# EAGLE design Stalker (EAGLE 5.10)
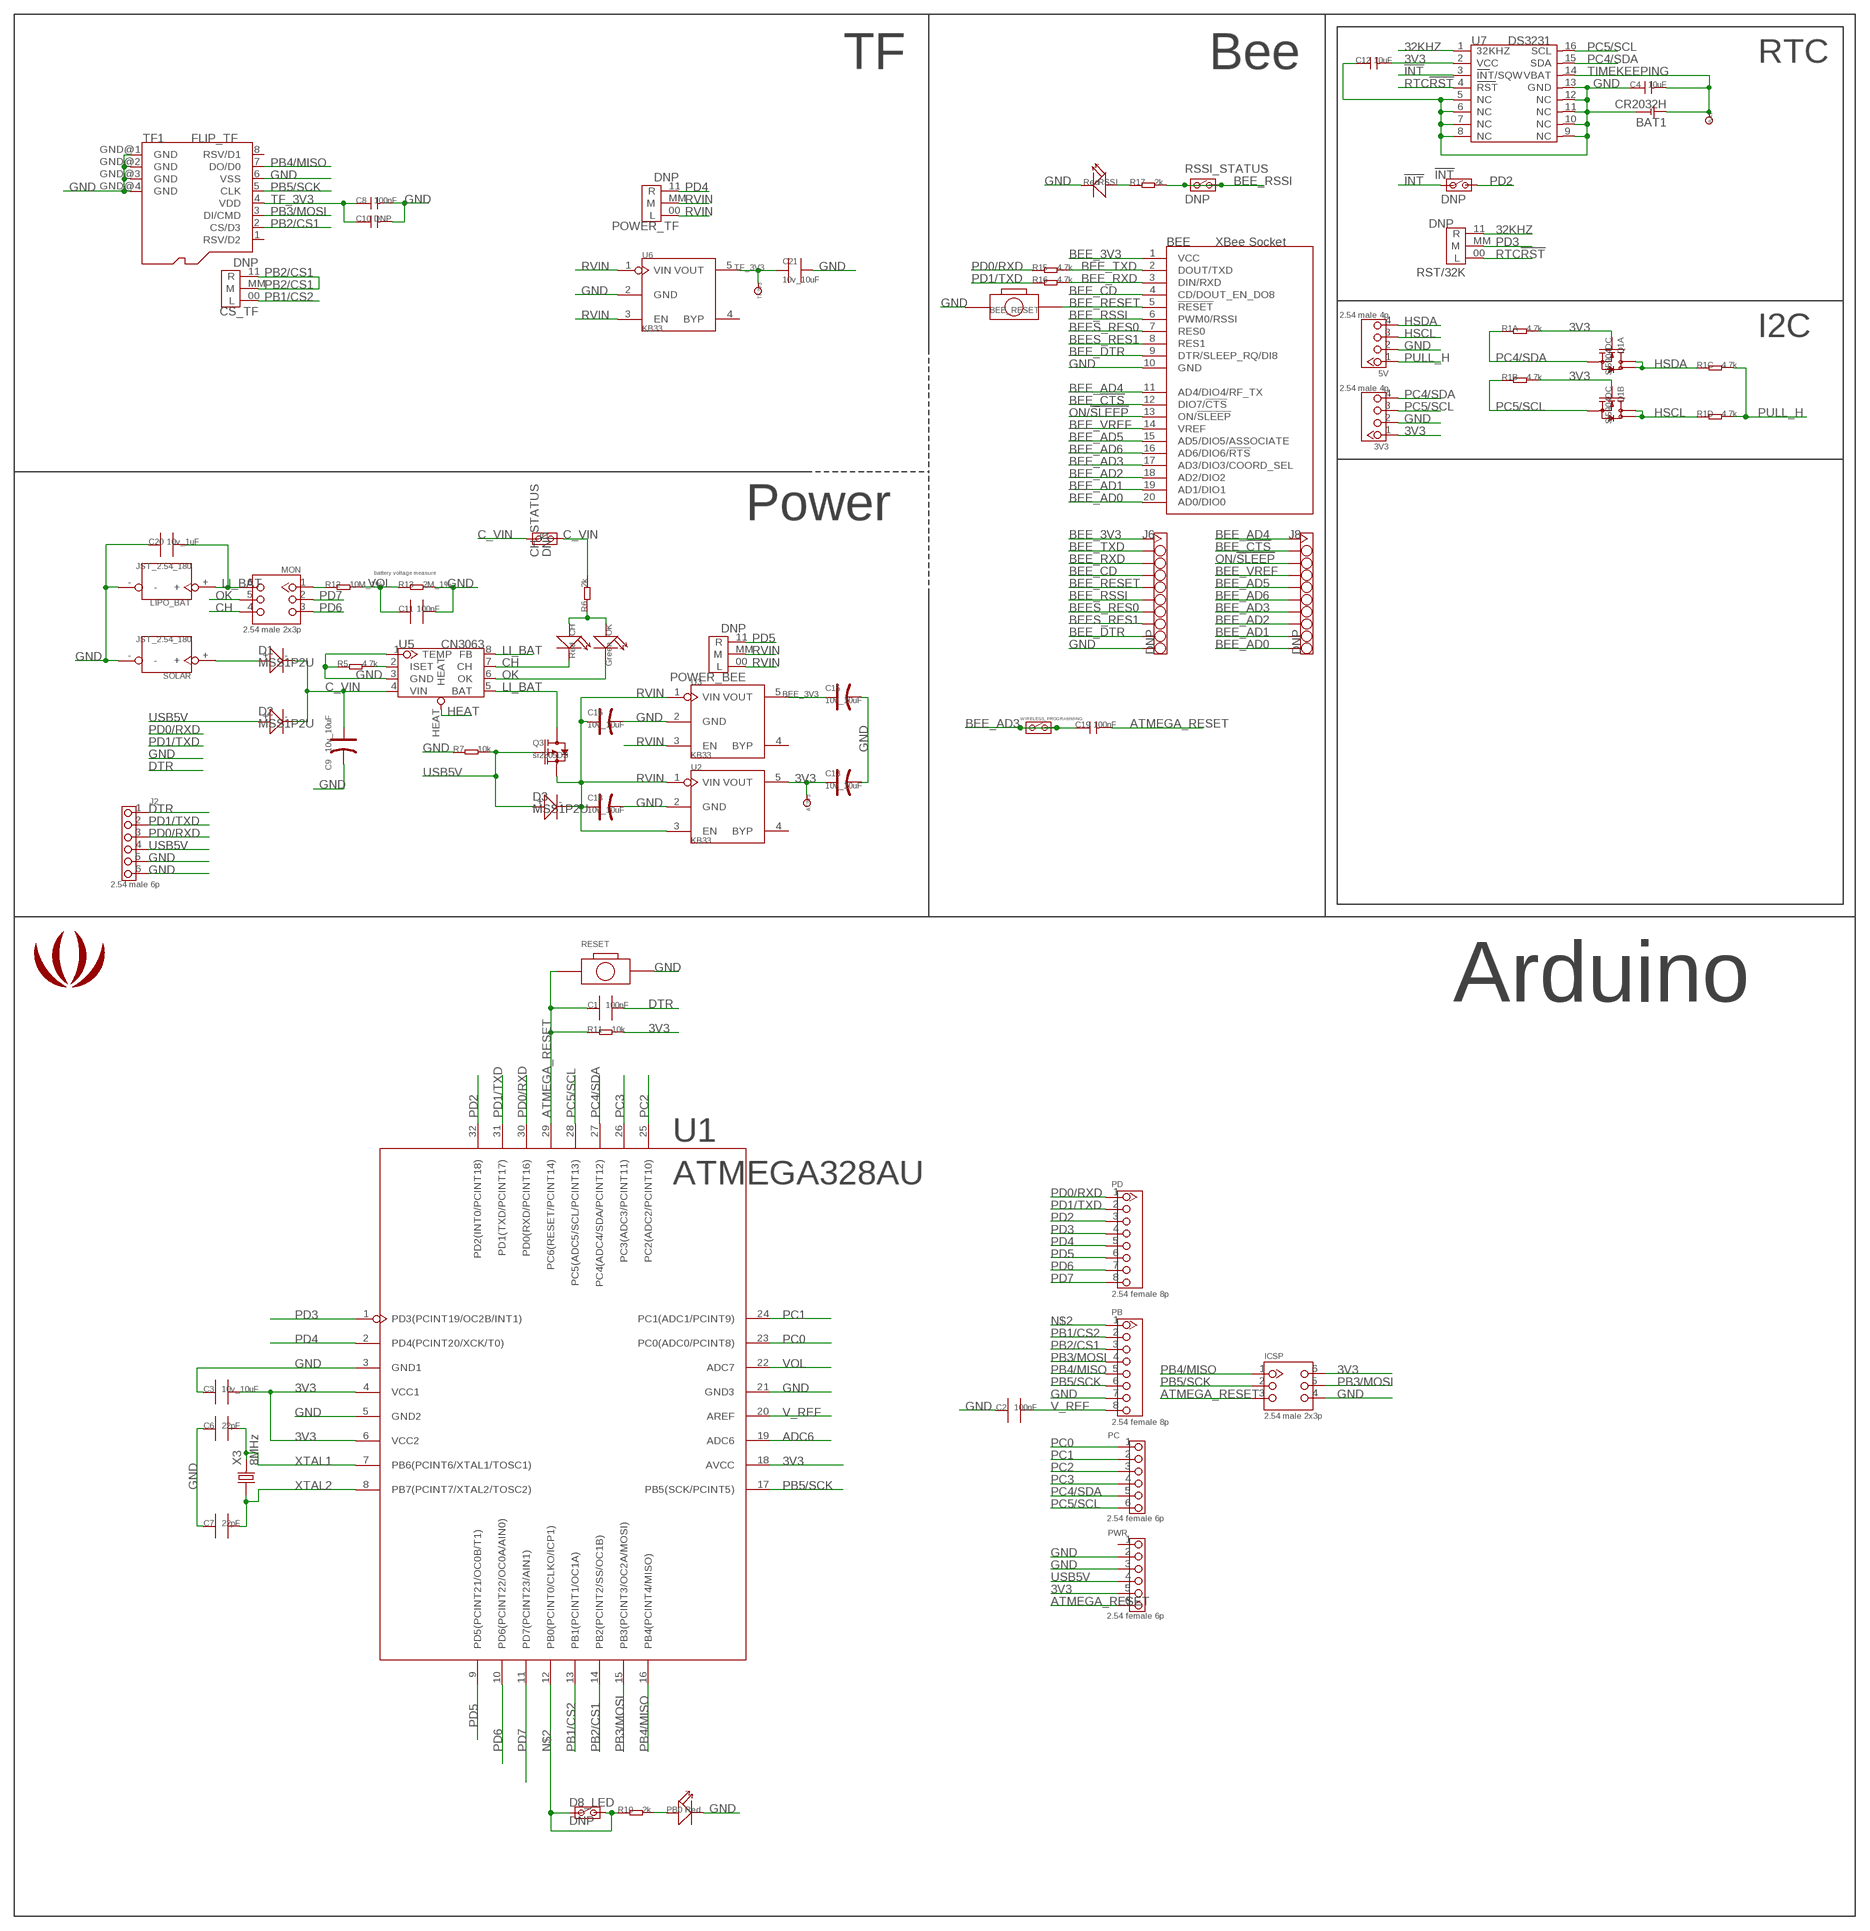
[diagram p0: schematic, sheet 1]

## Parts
3V3  2.54 male 4p  HEADER-4P-2.54  [4P-2.54-LEADED]
5V  2.54 male 4p  HEADER-4P-2.54  [4P-2.54-LEADED]
!INT  DNP  JP_SW  [JP_SW]
AT3V3  DNP  TEST_POINT_SIZE_3030  [TP_3535]
BAT  DNP  TEST_POINT_SIZE_3030  [TP_3535]
BAT1  CR2032H  [CR2032H]
BEE  XBee Socket  BEEO  [BEE]
BEE_RESET  3.8x6.1 button  BOTTON_1_SMD  [BOTTON_1]
C1  100nF  006-C0603  [0603@1]
C2  100nF  006-C0603  [0603@1]
C3  10v_10uF  006-C0805  [0805@1]
C4  10uF  C-0805  [0805]
C6  22pF  006-C0603  [0603@1]
C7  22pF  006-C0603  [0603@1]
C8  100nF  C-0603  [0603]
C9  10v_10uF  006-CAP_AVX_B  [AVX_B]
C10  DNP  C-0603  [0603]
C11  100nF  006-C0603  [0603@1]
C12  10uF  C-0805  [0805]
C13  10v_10uF  006-CAP_AVX_B  [AVX_B]
C15  10v_10uF  006-CAP_AVX_B  [AVX_B]
C16  10v_10uF  006-CAP_AVX_B  [AVX_B]
C18  10v_10uF  006-CAP_AVX_B  [AVX_B]
C19  100nF  C-0603  [0603]
C20  10v_1uF  006-C0805  [0805@1]
C21  10v_10uF  006-C0805  [0805@1]
CH  Red  007-LED0603  [D0603]
CH_STATUS  DNP  JP_SW  [JP_SW]
CS_TF  DNP  JUMPER  [JUMPER]
D1  MSS1P2U  010-DMSS1P2U  [D1005]
D2  MSS1P2U  010-DMSS1P2U  [D1005]
D3  MSS1P2U  010-DMSS1P2U  [D1005]
D8_LED  DNP  JP_SW  [JP_SW]
ICSP  2.54 male 2x3p  HEADER-2X3P-2.54  [2X3P-2.54-LEADED]
J2  2.54 male 6p  HEADER-6P-LEADED-2.54  [6P-2.54-LEADED]
J6  DNP  HEADER_1X10DD  [HEADER_1X10]
J8  DNP  HEADER_1X10DD  [HEADER_1X10]
LIPO_BAT  JST_2.54_180  PWR2P_180  [PWR_1X2]
LOGO1  LOGO  [LOGO_RO]
MON  2.54 male 2x3p  HEADER-2X3P-2.54  [2X3P-2.54-LEADED]
OK  Green  007-LED0603  [D0603]
PB  2.54 female 8p  HEADER-8P-2.54-LEADED  [8P-2.54-LEADED]
PB0  Red  007-LED0603  [D0603]
PC  2.54 female 6p  HEADER-6P-LEADED-2.54  [6P-2.54-LEADED]
PD  2.54 female 8p  HEADER-8P-2.54-LEADED  [8P-2.54-LEADED]
POWER_BEE  DNP  JUMPER  [JUMPER]
POWER_TF  DNP  JUMPER  [JUMPER]
PWR  2.54 female 6p  HEADER-6P-LEADED-2.54  [6P-2.54-LEADED]
Q1  Si5904DC  010-DUAL-N-MOSFET_1206-8  [1206-8]
Q3  si2305DS  010-P-MOSFETSOT23  [SOT23]
R1  4.7k  005-4R_1206  [R1206-8]
R5  4.7k  005-R0603  [0603@1]
R6  2k  005-R0603  [0603@1]
R7  10k  005-R0603  [0603@1]
R10  2k  005-R0603  [0603@1]
R11  10k  005-R0603  [0603@1]
R12  10M_1%  005-R0603  [0603@1]
R13  2M_1%  005-R0603  [0603@1]
R15  4.7k  005-R0603  [0603@1]
R16  4.7k  005-R0603  [0603@1]
R17  2k  005-R0603  [0603@1]
RESET  3.8x6.1 button  BOTTON_1_SMD  [BOTTON_1]
RSSI  Red  007-LED0603  [D0603]
RSSI_STATUS  DNP  JP_SW  [JP_SW]
RST/32K  DNP  JUMPER  [JUMPER]
SOLAR  JST_2.54_180  PWR2P_180  [PWR_1X2]
TF1  FLIP_TF  [FLIP_TF]
TF3V3  DNP  TEST_POINT_SIZE_3030  [TP_3535]
U1  ATMEGA328AU  ATMEGA168-20AU  [ATMEGA168-20AU]
U2  KB33  MIC5025_X.X  [SOT23-5]
U3  KB33  MIC5025_X.X  [SOT23-5]
U5  CN3063  CN3083  [SOP8]
U6  KB33  MIC5025_X.X  [SOT23-5]
U7  DS3231  [SO16-W]
WIRELESS_PROGRAMMING  DNP  JP_SW  [JP_SW]
X3  8MHz  011-CRYSTALHC49S  [HC49/S]

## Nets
3V3: 3V3.1 AT3V3.T C3.2 C12.2 C13.+ ICSP.6 PWR.5 Q1.2(A:G) Q1.4(B:G) R1.7 R1.8 R11.2 U1.4(VCC1) U1.6(VCC2) U1.18(AVCC) U2.5(VOUT) U7.2(VCC)
32KHZ: RST/32K.11(R) U7.1(32KHZ)
!INT: !INT.1 U7.3(INT/SQW)
ADC6: U1.19(ADC6)
ATMEGA_RESET: C1.1 C19.2 ICSP.3 PWR.6 R11.1 RESET.1 U1.29(PC6(RESET/PCINT14))
BEE_3V3: BEE.1(VCC) C15.+ J6.1 U3.5(VOUT)
BEE_!CTS: BEE.12(DIO7/!CTS) J8.2
BEE_AD0: BEE.20(AD0/DIO0) J8.10
BEE_AD1: BEE.19(AD1/DIO1) J8.9
BEE_AD2: BEE.18(AD2/DIO2) J8.8
BEE_AD3: BEE.17(AD3/DIO3/COORD_SEL) C19.1 J8.7 WIRELESS_PROGRAMMING.1 WIRELESS_PROGRAMMING.2
BEE_AD4: BEE.11(AD4/DIO4/RF_TX) J8.1
BEE_AD5: BEE.15(AD5/DIO5/ASSOCIATE) J8.5
BEE_AD6: BEE.16(AD6/DIO6/!RTS) J8.6
BEE_CD: BEE.4(CD/DOUT_EN_DO8) J6.4
BEE_DTR: BEE.9(DTR/SLEEP_RQ/DI8) J6.9
BEE_RESET: BEE.5(!RESET) BEE_RESET.P$2 J6.5
BEE_RSSI: BEE.6(PWM0/RSSI) J6.6 R17.2 RSSI_STATUS.1 RSSI_STATUS.2
BEE_RXD: BEE.3(DIN/RXD) J6.3 R16.2
BEE_TXD: BEE.2(DOUT/TXD) J6.2 R15.2
BEE_VREF: BEE.14(VREF) J8.4
BEES_RES0: BEE.7(RES0) J6.7
BEES_RES1: BEE.8(RES1) J6.8
C_VIN: C9.+ CH_STATUS.1 CH_STATUS.2 D1.- D2.- R6.2 U5.4(VIN)
CH: CH.- MON.4 U5.7(CH)
DTR: C1.2 J2.1
GND: 3V3.2 5V.2 BAT1.- BEE.10(GND) BEE_RESET.1 C2.1 C3.1 C4.1 C6.1 C7.1 C8.2 C9.- C10.2 C11.2 C12.1 C13.- C15.- C16.- C18.- C20.1 C21.2 ICSP.4 J2.5 J2.6 J6.10 LIPO_BAT.- PB0.- PB.7 PWR.2 PWR.3 R5.1 R7.1 R13.2 RESET.P$2 RSSI.- SOLAR.- TF1.6(VSS) TF1.GND@1(GND) TF1.GND@2(GND) TF1.GND@3(GND) TF1.GND@4(GND) U1.3(GND1) U1.5(GND2) U1.21(GND3) U2.2(GND) U3.2(GND) U5.1(TEMP) U5.3(GND) U6.2(GND) U7.5(NC) U7.6(NC) U7.7(NC) U7.8(NC) U7.9(NC) U7.10(NC) U7.11(NC) U7.12(NC) U7.13(GND)
HEAT: U5.HEAT
HSCL: 5V.3 Q1.5(B:D) Q1.6(B:D) R1.4
HSDA: 5V.4 Q1.7(A:D) Q1.8(A:D) R1.3
LI_BAT: C20.2 LIPO_BAT.+ MON.6 Q3.3(D) U5.5(BAT) U5.8(FB)
N$1: PB0.+ R10.2
N$2: D8_LED.1 D8_LED.2 PB.1 R10.1 U1.12(PB0(PCINT0/CLKO/ICP1))
N$3: D1.+ SOLAR.+
N$5: R5.2 U5.2(ISET)
N$6: R17.1 RSSI.+
N$8: CH.+ OK.+ R6.1
N$15: MON.1 R12.1
OK: MON.5 OK.- U5.6(OK)
ON/!SLEEP: BEE.13(ON/!SLEEP) J8.3
PB1/CS2: CS_TF.00(L) PB.2 U1.13(PB1(PCINT1/OC1A))
PB2/CS1: CS_TF.11(R) CS_TF.MM(M) PB.3 TF1.2(CS/D3) U1.14(PB2(PCINT2/SS/OC1B))
PB3/MOSI: ICSP.5 PB.4 TF1.3(DI/CMD) U1.15(PB3(PCINT3/OC2A/MOSI))
PB4/MISO: ICSP.1 PB.5 TF1.7(DO/D0) U1.16(PB4(PCINT4/MISO))
PB5/SCK: ICSP.2 PB.6 TF1.5(CLK) U1.17(PB5(SCK/PCINT5))
PC0: PC.1 U1.23(PC0(ADC0/PCINT8))
PC1: PC.2 U1.24(PC1(ADC1/PCINT9))
PC2: PC.3 U1.25(PC2(ADC2/PCINT10))
PC3: PC.4 U1.26(PC3(ADC3/PCINT11))
PC4/SDA: 3V3.4 PC.5 Q1.1(A:S) R1.1 U1.27(PC4(ADC4/SDA/PCINT12)) U7.15(SDA)
PC5/SCL: 3V3.3 PC.6 Q1.3(B:S) R1.2 U1.28(PC5(ADC5/SCL/PCINT13)) U7.16(SCL)
PD0/RXD: J2.3 PD.1 R15.1 U1.30(PD0(RXD/PCINT16))
PD1/TXD: J2.2 PD.2 R16.1 U1.31(PD1(TXD/PCINT17))
PD2: !INT.2 PD.3 U1.32(PD2(INT0/PCINT18))
PD3: PD.4 RST/32K.MM(M) U1.1(PD3(PCINT19/OC2B/INT1))
PD4: PD.5 POWER_TF.11(R) U1.2(PD4(PCINT20/XCK/T0))
PD5: PD.6 POWER_BEE.11(R) U1.9(PD5(PCINT21/OC0B/T1))
PD6: MON.3 PD.7 U1.10(PD6(PCINT22/OC0A/AIN0))
PD7: MON.2 PD.8 U1.11(PD7(PCINT23/AIN1))
PULL_H: 5V.1 R1.5 R1.6
RTC!RST: RST/32K.00(L) U7.4(RST)
RVIN: C16.+ C18.+ D3.- POWER_BEE.00(L) POWER_BEE.MM(M) POWER_TF.00(L) POWER_TF.MM(M) Q3.2(S) U2.1(VIN) U2.3(EN) U3.1(VIN) U3.3(EN) U6.1(VIN) U6.3(EN)
TF_3V3: C8.1 C10.1 C21.1 TF1.4(VDD) TF3V3.T U6.5(VOUT)
TIMEKEEPING: BAT1.+ BAT.T C4.2 U7.14(VBAT)
USB5V: D2.+ D3.+ J2.4 PWR.4 Q3.1(G) R7.2
V_REF: C2.2 PB.8 U1.20(AREF)
VOL: C11.1 R12.2 R13.1 U1.22(ADC7)
XTAL1: C6.2 U1.7(PB6(PCINT6/XTAL1/TOSC1)) X3.2
XTAL2: C7.2 U1.8(PB7(PCINT7/XTAL2/TOSC2)) X3.1
Unconnected: PWR.1 TF1.1(RSV/D2) TF1.8(RSV/D1) U2.4(BYP) U3.4(BYP) U6.4(BYP)

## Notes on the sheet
- TF | Bee | RTC
- I2C
- Power
- battery voltage measure
- Arduino

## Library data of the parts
3V3 5V = Connector:HEADER-4P
!INT CH_STATUS D8_LED RSSI_STATUS WIRELESS_PROGRAMMING = CPT_SMD:JP_SW
AT3V3 BAT TF3V3 = For_Test_Albert:TEST_POINT
BAT1 = BAT:CR2032H
BEE = EXT_moudle:BEE
BEE_RESET RESET = CPT_SMD:BOTTON_1
C1-C3 C6 C7 C11 C20 C21 = Discrete:006-C*: Ceramic Capacitors
C4 C8 C10 C12 C19 = Discrete:C*: Ceramic Capacitors
C9 C13 C15 C16 C18 = Discrete:006-CAP*: Electrolytic Capacitors,Tantalum Capacitors and Super Capacitors
CH OK PB0 RSSI = Discrete:007-LED*
CS_TF POWER_BEE POWER_TF RST/32K = CPT_SMD:JUMPER
D1-D3 = Discrete:010-D*
ICSP MON = Connector:HEADER-2X3P
J2 PC PWR = Connector:HEADER-6P
J6 J8 = CONNECTER:HEADER_1X10
LIPO_BAT SOLAR = CONNECTER:PWR2P
LOGO1 = logo:LOGO
PB PD = Connector:HEADER-8P
Q1 = Discrete:010-DUAL-N-MOSFET*: Si5902BDC Si5904DC Si5908DC Si5920DC
Q3 = Discrete:010-P-MOSFET*: Si2305DS Si2323CDS
R1 = Discrete:005-4R*: Resistor Array
R5-R7 R10-R13 R15-R17 = Discrete:005-R*
TF1 = Holders:FLIP_TF: http://garden.seeedstudio.com/images/e/e4/Flip_TF_Holder.jpg
U1 = IC_SMD:ATMEGA168-20AU
U2 U3 U6 = ICs_v54:MIC5025_X.X
U5 = ICs_v54:CN3083
U7 = IC:DS3231
X3 = Discrete:011-CRYSTAL*: CRYSTAL

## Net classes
0 default: width 0.152 mm, drill 0.305 mm, clearance 0.152 mm

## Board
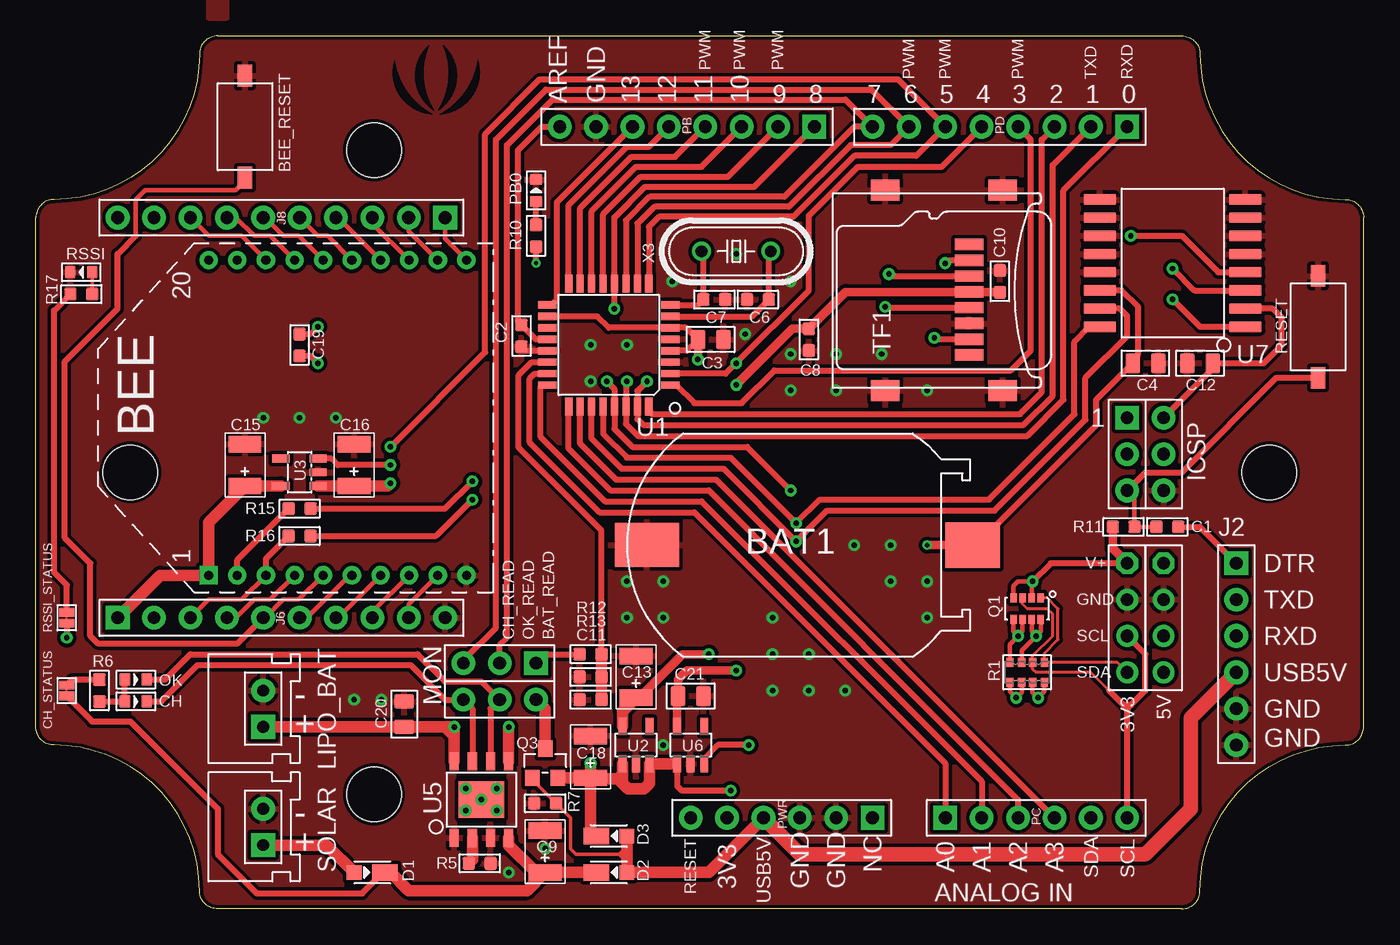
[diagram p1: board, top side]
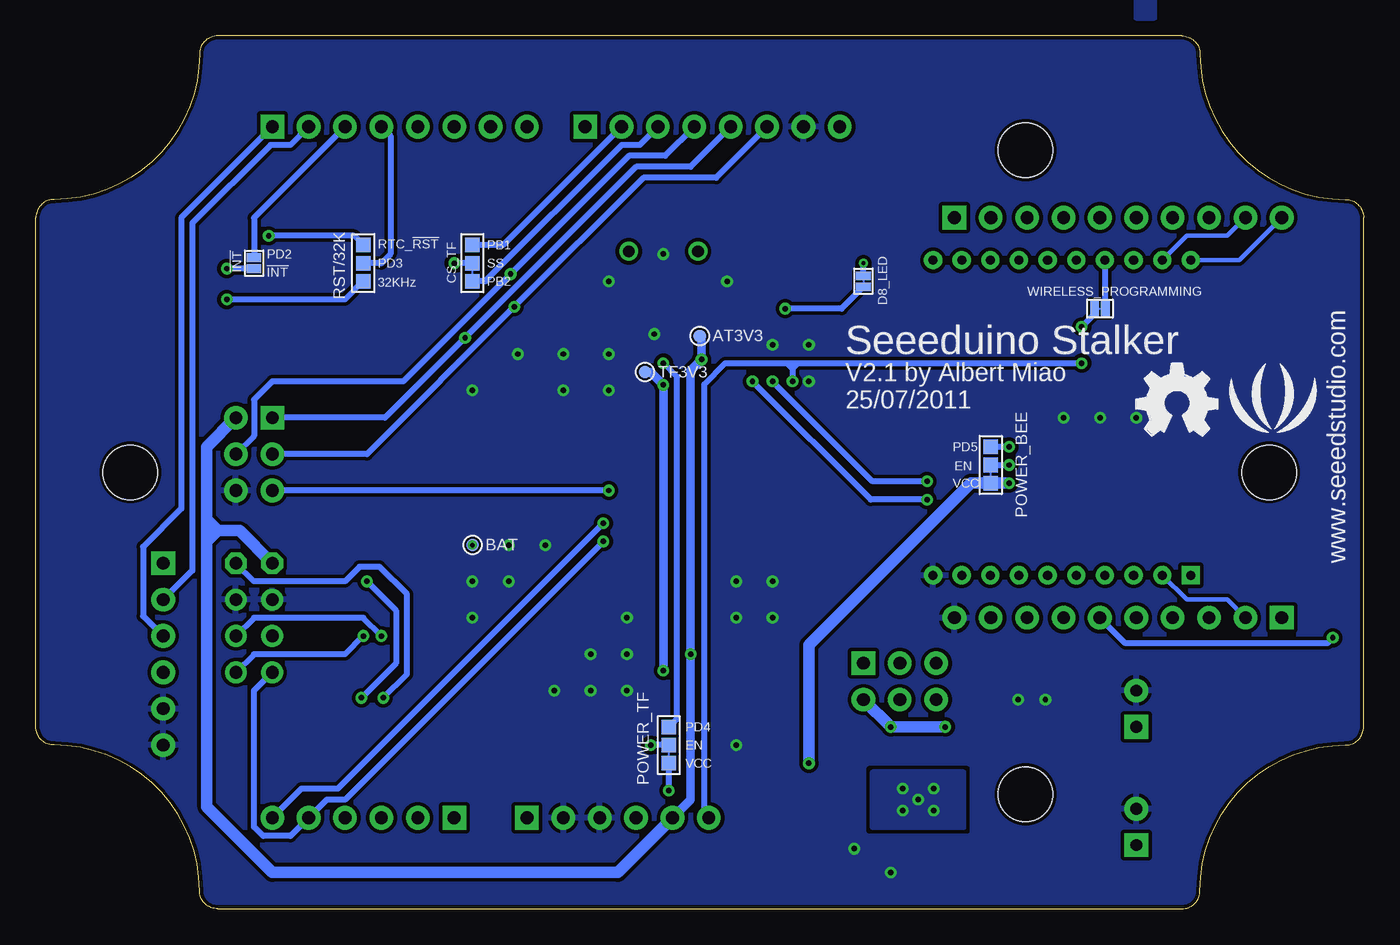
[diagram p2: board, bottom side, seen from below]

Size 92.71 x 60.96 mm. Coordinates in mm from the lower left corner, seen from the top.
Outline: 12.7,60.96 arc90 11.43,59.69 arc-90 1.27,49.53 arc90 0,48.26 0,12.7 arc90 1.27,11.43 arc-90 11.43,1.27 arc90 12.7,0 80.01,0 arc90 81.28,1.27 arc-90 91.44,11.43 arc90 92.71,12.7 92.71,48.26 arc90 91.44,49.53 arc-90 81.28,59.69 arc90 80.01,60.96 12.7,60.96
Copper layers (1*16): Top 0.035mm / dielectric 1.5mm / Bottom 0.035mm
Design rules "SeeedStudio_rule_no_angle_090911 *": minimum track width 6mil, minimum drill 12mil, track to track 6mil, track to pad 6mil, pad to pad 6mil, via to via 6mil, smd to smd 0mil, copper to edge 10mil, drill to drill 10mil, minimum pad ring 10mil, minimum via ring 6mil, stop-mask expansion 2mil, vias tented up to drill 25mil, thermal gap 10mil
Holes 3.81 mm at 23.61,52.98 86.11,30.48 6.61,30.48 23.61,7.98
tRestrict: area 73.7,43.2 to 74.9,48.9; area 83.8,43.2 to 85.1,48.9

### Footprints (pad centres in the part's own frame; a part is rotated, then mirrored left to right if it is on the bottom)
4P-2.54-LEADED = drill 0.889 pad 1.524 octagon: 1 0,3.81 | drill 0.889 pad 1.524 round: 2 0,1.27; 3 0,-1.27; 4 0,-3.81
JP_SW = smd 1.016 x 0.61: 1 0,0.381; 2 0,-0.381
TP_3535 = smd 0.889 x 0.889: T 0,0
CR2032H = smd 3.81 x 3.175: + 12.7,0 | smd 4.445 x 3.048: - -10.033,0
BEE = drill 0.635 pad 1.27 square: 1 -11,0 | drill 0.635 pad 1.27 round: 2 -11,-2; 3 -11,-4; 4 -11,-6; 5 -11,-8; 6 -11,-10; 7 -11,-12; 8 -11,-14; 9 -11,-16; 10 -11,-18; 11 11,-18; 12 11,-16; 13 11,-14; 14 11,-12; 15 11,-10; 16 11,-8; 17 11,-6; 18 11,-4; 19 11,-2; 20 11,0
BOTTON_1 = smd 1.524 x 1.016: 1 -3.556,0; P$2 3.556,0
0603@1 = smd 0.889 x 0.889: 1 -0.762,0; 2 0.762,0
0805@1 = smd 1.016 x 1.397: 1 -0.889,0; 2 0.889,0
0805 = smd 1.016 x 1.397: 1 -0.889,0; 2 0.889,0
0603 = smd 0.889 x 0.889: 1 -0.762,0; 2 0.762,0
AVX_B = smd 1.143 x 2.286: + -1.46,0; - 1.46,0
D0603 = smd 0.762 x 0.889: + -0.762,0; - 0.762,0
JUMPER = smd 1.016 x 1.016: 00 -1.27,0; 11 1.27,0; MM 0,0
D1005 = smd 1.016 x 1.016: + 1.27,0 | smd 1.778 x 1.143: - -0.889,0
2X3P-2.54-LEADED = drill 0.889 pad 1.651 square: 1 -1.27,2.54 | drill 0.889 pad 1.651 round: 2 -1.27,0; 3 -1.27,-2.54; 4 1.27,-2.54; 5 1.27,0; 6 1.27,2.54
6P-2.54-LEADED = drill 0.889 pad 1.651 square: 1 0,6.35 | drill 0.889 pad 1.651 round: 2 0,3.81; 3 0,1.27; 4 0,-1.27; 5 0,-3.81; 6 0,-6.35
HEADER_1X10 = drill 0.889 pad 1.651 square: 1 0,11.43 | drill 0.889 pad 1.651 round: 2 0,8.89; 3 0,6.35; 4 0,3.81; 5 0,1.27; 6 0,-1.27; 7 0,-3.81; 8 0,-6.35; 9 0,-8.89; 10 0,-11.43
PWR_1X2 = drill 0.813 pad 1.651 square: + 1.27,0 | drill 0.813 pad 1.651 round: - -1.27,0
8P-2.54-LEADED = drill 0.889 pad 1.651 square: 1 0,8.89 | drill 0.889 pad 1.651 round: 2 0,6.35; 3 0,3.81; 4 0,1.27; 5 0,-1.27; 6 0,-3.81; 7 0,-6.35; 8 0,-8.89
1206-8 = smd 0.457 x 0.635: 1 -0.953,-0.762; 2 -0.318,-0.762; 3 0.318,-0.762; 4 0.953,-0.762; 5 0.953,0.762; 6 0.318,0.762; 7 -0.318,0.762; 8 -0.953,0.762
SOT23 = smd 1.016 x 1.143: 1 -0.889,-1.016; 2 0.889,-1.016; 3 0,1.016
R1206-8 = smd 0.508 x 0.635: 1 -1.206,-0.699; 2 -0.381,-0.699; 3 0.381,-0.699; 4 1.206,-0.699; 5 1.206,0.699; 6 0.381,0.699; 7 -0.381,0.699; 8 -1.206,0.699
FLIP_TF = smd 0.8 x 2: 1 3.2,0.25; 2 2.1,0.25; 3 1,0.25; 4 -0.1,0.25; 5 -1.2,0.25; 6 -2.3,0.25; 7 -3.4,0.25; 8 -4.5,0.25 | smd 1.45 x 2: GND@1 -7,6.1; GND@2 -7,-2.1; GND@3 7,-2.1; GND@4 7,6.1
ATMEGA168-20AU = smd 1.27 x 0.508: 1 -4.293,2.8; 2 -4.293,2; 3 -4.293,1.2; 4 -4.293,0.4; 5 -4.293,-0.4; 6 -4.293,-1.2; 7 -4.293,-2; 8 -4.293,-2.8; 17 4.293,-2.8; 18 4.293,-2; 19 4.293,-1.2; 20 4.293,-0.4; 21 4.293,0.4; 22 4.293,1.2; 23 4.293,2; 24 4.293,2.8 | smd 0.508 x 1.27: 9 -2.8,-4.293; 10 -2,-4.293; 11 -1.2,-4.293; 12 -0.4,-4.293; 13 0.4,-4.293; 14 1.2,-4.293; 15 2,-4.293; 16 2.8,-4.293; 25 2.8,4.293; 26 2,4.293; 27 1.2,4.293; 28 0.4,4.293; 29 -0.4,4.293; 30 -1.2,4.293; 31 -2,4.293; 32 -2.8,4.293
SOT23-5 = smd 0.55 x 1.2: 1 -0.95,-1.3; 2 0,-1.3; 3 0.95,-1.3; 4 0.95,1.3; 5 -0.95,1.3
SOP8 = smd 0.635 x 1.27: 1 -1.905,-2.667; 2 -0.635,-2.667; 3 0.635,-2.667; 4 1.905,-2.667; 5 1.905,2.667; 6 0.635,2.667; 7 -0.635,2.667; 8 -1.905,2.667 | smd 3.175 x 2.54: HEAT 0,0
SO16-W = smd 0.762 x 2.286: 1 -4.445,-5.08; 2 -3.175,-5.08; 3 -1.905,-5.08; 4 -0.635,-5.08; 5 0.635,-5.08; 6 1.905,-5.08; 7 3.175,-5.08; 8 4.445,-5.08; 9 4.445,5.08; 10 3.175,5.08; 11 1.905,5.08; 12 0.635,5.08; 13 -0.635,5.08; 14 -1.905,5.08; 15 -3.175,5.08; 16 -4.445,5.08
HC49/S = drill 0.813 round: 1 -2.413,0; 2 2.413,0

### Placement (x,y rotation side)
3V3  76.2,20.32 0 top
5V  78.74,20.32 0 top
!INT  77.47,45.09 180 bottom
AT3V3  46.35,40.01 0 bottom
BAT  62.23,25.4 0 bottom
BAT1  52.7,25.4 0 top
BEE  12.06,34.29 90 top
BEE_RESET  14.61,54.61 270 top
C1  78.99,26.67 0 top
C2  33.91,40.01 90 top
C3  47.12,39.75 180 top
C4  77.47,38.1 180 top
C6  50.42,42.55 0 top
C7  47.37,42.55 180 top
C8  53.98,39.75 270 top
C9  35.56,4 90 top
C10  67.31,43.81 90 top
C11  38.73,14.61 180 top
C12  81.28,38.1 0 top
C13  41.91,16.19 90 top
C15  14.61,30.99 90 top
C16  22.23,30.99 90 top
C18  38.73,10.6 90 top
C19  18.41,39.37 270 top
C20  25.72,13.59 270 top
C21  45.72,14.86 0 top
CH  6.99,14.48 0 top
CH_STATUS  2.16,15.24 180 top
CS_TF  62.23,45.09 270 bottom
D1  23.5,2.54 180 top
D2  40.01,2.54 0 top
D3  40.01,5.08 0 top
D8_LED  34.92,43.81 180 bottom
ICSP  77.47,31.75 0 top
J2  83.82,17.78 0 top
J6  17.14,20.32 90 top
J8  17.14,48.26 270 top
LIPO_BAT  15.88,13.97 270 top
LOGO1  27.94,57.15 0 top
MON  32.38,15.88 270 top
OK  6.99,16 0 top
PB  45.47,54.61 270 top
PB0  34.92,50.16 90 top
PC  69.85,6.35 90 top
PD  67.31,54.61 270 top
POWER_BEE  26.04,30.99 90 bottom
POWER_TF  48.51,11.43 90 bottom
PWR  52.07,6.35 270 top
Q1  69.22,20.95 180 top
Q3  35.56,10.16 0 top
R1  69.22,16.51 180 top
R5  30.99,3.17 180 top
R6  4.45,15.24 90 top
R7  35.56,7.37 0 top
R10  34.92,46.99 90 top
R11  75.95,26.67 180 top
R12  38.73,17.78 0 top
R13  38.73,16.19 180 top
R15  18.41,27.94 180 top
R16  18.41,26.04 180 top
R17  3.17,42.93 180 top
RESET  89.53,40.64 90 top
RSSI  3.17,44.45 180 top
RSSI_STATUS  2.16,20.32 0 top
RST/32K  69.85,45.09 270 bottom
SOLAR  15.88,5.71 270 top
TF1  65.41,43.18 90 top
TF3V3  50.16,37.47 0 bottom
U1  40.01,39.37 180 top
U2  41.91,11.43 0 top
U3  18.41,30.48 90 top
U5  31.11,7.62 0 top
U6  45.72,11.43 0 top
U7  79.38,45.09 90 top
U$1  [OSHW_FILLX200_NOTEXT]  15.88,33.02 0 bottom
U$2  [LOGO_SILK]  6.35,34.92 0 bottom
WIRELESS_PROGRAMMING  18.41,41.91 270 bottom
X3  48.9,45.91 0 top

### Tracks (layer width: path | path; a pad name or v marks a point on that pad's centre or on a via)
3V3  (via drill 0.38 pad 0.81)
  Top 0.305: Q1.2 69.53,22.8 v69.6,22.86 68.58,22.86 68.26,22.54 Q1.4 | R1.8 70.42,15.18 v69.98,14.73 69.6,15.11 R1.7
  Top 0.406: U1.4 45.45,38.97 C3.2 45.41,40.57 U1.6 40.01,40.57 39.21,41.37 U1.18 | 3V3.1 70.87,24.13 v69.6,22.86 | ICSP.6 82.17,37.72 C12.2 85.72,38.1 87,39.37 87,41.27 86.36,41.91 U7.2
  Top 0.61: 3V3.1 75.18,25.15 R11.2 | v46.99,17.78 45.15,17.78 42.1,14.73 C13.+ | v46.23,38.35 C3.2
  Top 0.813: U2.5 40.96,13.78 C13.+
  Bottom 0.406: v69.6,22.86 67.56,20.83 67.56,17.14 v69.98,14.73
  Bottom 0.61: PWR.5 46.99,7.62 v46.99,17.78 46.99,37.59 v46.23,38.35 46.23,39.88 AT3V3.T
  Bottom 0.813: 80.77,25.65 80.77,26.42 | 80.77,26.42 80.77,27.18 | 80.77,27.18 80.77,32.26 ICSP.6 | 3V3.1 78.49,26.42 80.01,26.42 | 80.77,26.42 80.01,26.42 | 80.01,26.42 80.77,27.18 | 80.77,25.65 80.01,26.42 | 80.77,25.65 80.77,7.11 76.2,2.54 52.07,2.54 PWR.5
  pour Bottom: 14.61,63.5 15.88,63.5 15.88,62.23 14.61,62.23
32KHZ  (via drill 0.38 pad 0.81)
  Top 0.406: U7.1 81.28,40.64 v79.38,42.55
  Bottom 0.406: v79.38,42.55 71.12,42.55 RST/32K.11
!INT  (via drill 0.38 pad 0.81)
  Top 0.406: U7.3 80.9,43.18 v79.38,44.7
  Bottom 0.406: !INT.1 v79.38,44.7
ATMEGA_RESET  (via drill 0.38 pad 0.81)
  Top 0.305: C1.1 R11.1 76.71,28.7 ICSP.3
  Top 0.406: v39.88,36.83 40.41,36.3 U1.29 40.41,33.51 41.66,32.26 49.66,32.26 v52.7,29.21 | ICSP.3 77.47,30.48 80.01,30.48 86.61,37.08 RESET.1 | C19.2 19.18,38.61 v19.68,38.1
  Bottom 0.406: PWR.6 46.04,6.67 46.04,36.64 44.58,38.1 40.26,38.1 | 40.26,38.1 39.5,38.1 | 39.88,37.72 v39.88,36.83 | 39.5,38.1 39.88,37.72 | 40.26,38.1 39.88,37.72 | v52.7,29.21 ICSP.3 | 39.5,38.1 v19.68,38.1
BEE_3V3
  Top 0.813: U3.5 C15.+ 12.06,26.99 BEE.1 8.69,23.29 J6.1
BEE_!CTS
  Top 0.305: BEE.12 26.04,47.32 J8.2
BEE_AD0
  Bottom 0.305: BEE.20 8.69,45.29 J8.10
BEE_AD1
  Bottom 0.305: BEE.19 12.37,46.99 9.53,46.99 J8.9
BEE_AD2
  Top 0.305: BEE.18 14.37,46.99 12.06,46.99 J8.8
BEE_AD3  (via drill 0.38 pad 0.81)
  Top 0.305: BEE.17 16.36,46.99 15.24,46.99 13.97,48.26 J8.7
  Top 0.406: C19.1 19.18,40.13 v19.68,40.64
  Bottom 0.152: WIRELESS_PROGRAMMING.2 WIRELESS_PROGRAMMING.1
  Bottom 0.406: WIRELESS_PROGRAMMING.1 18.03,45.26 BEE.17 | WIRELESS_PROGRAMMING.2 18.8,41.53 v19.68,40.64
BEE_AD4
  Top 0.305: BEE.11 28.57,46.78 J8.1
BEE_AD5
  Top 0.305: BEE.15 20.36,46.99 19.68,46.99 J8.5
BEE_AD6
  Top 0.305: BEE.16 18.36,46.99 17.27,46.99 16,48.26 J8.6
BEE_CD
  Top 0.305: BEE.4 16.36,21.59 15.24,21.59 13.97,20.32 J6.4
BEE_DTR
  Top 0.305: J6.9 26.04,21.26 BEE.9
BEE_RESET
  Top 0.305: 6.99,46.99 6.99,49.53 7.62,50.16 13.97,50.16 14.61,50.8 BEE_RESET.P$2 | BEE.5 18.36,21.59 17.27,21.59 16,20.32 J6.5
  Top 0.406: J6.5 14.1,18.54 4.32,18.54 3.81,19.05 3.81,24.13 2.03,25.91 2.03,38.23 5.71,41.91 5.71,45.72 6.99,46.99
BEE_RSSI  (via drill 0.38 pad 0.81)
  Top 0.152: RSSI_STATUS.2 RSSI_STATUS.1
  Top 0.305: J6.6 18.92,20.32 21.89,23.29 BEE.6
  Top 0.406: R17.2 1.27,41.78 1.27,23.5 2.16,22.61 RSSI_STATUS.1 | RSSI_STATUS.2 v2.16,18.92
  Bottom 0.406: J6.6 16.64,18.54 2.54,18.54 v2.16,18.92
BEE_RXD
  Top 0.305: BEE.3 14.37,21.59 12.06,21.59 J6.3
  Top 0.406: BEE.3 16.07,24.45 R16.2
BEE_TXD
  Top 0.406: BEE.2 14.06,24.35 R15.2
  Bottom 0.305: BEE.2 12.37,21.59 9.53,21.59 J6.2
BEE_VREF
  Top 0.305: BEE.14 21.09,48.26 J8.4
BEES_RES0
  Top 0.305: J6.7 21.09,20.32 BEE.7
BEES_RES1
  Top 0.305: J6.8 23.5,20.72 BEE.8
C_VIN
  Top 0.152: CH_STATUS.1 CH_STATUS.2
  Top 0.406: D1.- 24.26,2.54 22.8,1.08 15.43,1.08 12.7,3.81 12.7,6.99 6.6,13.08 3.94,13.08 CH_STATUS.1 | R6.2 2.54,16 CH_STATUS.2
  Top 0.813: C9.+ 34.29,1.27 26.04,1.27 24.77,2.54 D1.- | C9.+ 34.92,2.54 33.02,4.45 U5.4 | C9.+ D2.-
CH
  Top 0.406: CH.- 8.76,14.48 11.3,17.02 26.16,17.02 28.57,14.61 MON.4 30.48,13.97 U5.7
DTR
  Top 0.406: C1.2 81.28,26.67 J2.1
GND  (via drill 0.38 pad 0.81)
  Top 0.406: U1.21 34.18,38.97 C2.1
  other vias: 52.7,36.2 52.7,38.73 55.88,38.73 55.88,36.2 59.05,38.73 62.23,36.2 49.53,40.13 41.27,39.37 38.73,39.37 38.73,36.83 44.45,43.81 48.9,45.72 52.7,43.81 41.27,22.86 43.81,22.86 43.81,20.32 41.27,20.32 51.44,20.32 51.44,17.78 51.44,15.24 53.98,17.78 53.98,15.24 56.52,15.24 57.15,25.4 59.69,25.4 59.69,22.86 62.23,22.86 62.23,20.32 18.41,34.29 20.95,34.29 15.88,34.29 24.13,14.61 22.23,14.61 33.02,2.54 35.56,4.19 43.81,11.43
  pour Top (rank 6): 13.34,63.5 12.06,63.5 12.06,62.23 13.34,62.23
  pour Top (rank 6, no thermals): 24.13,60.96 31.75,60.96 31.75,56.52 29.84,54.61 26.04,54.61 24.13,56.52
  pour Bottom (isolate 0.254, rank 6): 0,60.96 92.71,60.96 92.71,0 0,0
  pour Top (isolate 0.254, rank 6): 0,60.96 92.71,60.96 92.71,0 0,0
HEAT  (via drill 0.38 pad 0.81)
  other vias: 30.04,8.38 30.04,6.86 32.19,6.86 32.19,8.38 31.11,7.62
  pour Bottom (isolate 0.254): 27.94,9.53 34.29,9.53 34.29,5.71 27.94,5.71
HSCL  (via drill 0.38 pad 0.81)
  Top 0.305: Q1.6 68.9,19.37 v68.58,19.05 | Q1.5 68.26,19.37 v68.58,19.05 | R1.4 68.01,18.48 v68.58,19.05
  Bottom 0.406: 5V.3 77.47,20.32 69.85,20.32 v68.58,19.05
HSDA  (via drill 0.38 pad 0.81)
  Top 0.305: Q1.7 69.53,19.37 v69.85,19.05 | Q1.8 70.17,19.37 v69.85,19.05 | R1.3 68.83,18.03 v69.85,19.05
  Bottom 0.406: 5V.4 77.47,17.78 71.12,17.78 v69.85,19.05
LI_BAT  (via drill 0.38 pad 0.81)
  Top 0.813: LIPO_BAT.+ C20.2 v29.21,12.7 | v33.02,12.7 U5.5 | Q3.3 35.56,13.97 MON.6 | v29.21,12.7 28.57,12.7 29.21,12.06 v29.21,12.7 | v29.21,12.7 U5.8
  Bottom 0.813: v29.21,12.7 v33.02,12.7 MON.6
N$1
  Top 0.406: R10.2 PB0.+
N$2  (via drill 0.3 pad 0.64, 0.38 pad 0.81)
  Top 0.406: PB.1 50.16,50.42 42.55,50.42 40.41,48.28 U1.12 40.41,41.93 v40.39,41.91 | v34.92,45.09 R10.1
  Bottom 0.152: D8_LED.2 D8_LED.1
  Bottom 0.406: v40.39,41.91 36.45,41.91 D8_LED.1 | D8_LED.2 v34.92,45.09
N$3
  Top 0.813: SOLAR.+ 20.32,4.45 D1.+
N$5
  Top 0.813: U5.2 30.48,3.43 R5.2
N$6
  Top 0.254: R17.1 RSSI.+
N$8
  Top 0.406: R6.1 CH.+ OK.+
N$15
  Top 0.406: R12.1 35.56,17.78 MON.1
OK
  Top 0.406: OK.- 9.02,16 10.79,17.78 26.67,17.78 28.57,15.88 31.11,15.88 MON.5 31.75,13.97 U5.6
ON/!SLEEP
  Top 0.305: BEE.13 23.5,47.86 J8.3
PB1/CS2
  Top 0.406: U1.13 39.6,48.49 42.23,51.12 48.32,51.12 PB.2
  Bottom 0.406: CS_TF.00 60.07,46.35 PB.2
PB2/CS1  (via drill 0.38 pad 0.81)
  Top 0.406: U1.14 38.8,48.71 41.91,51.82 46.48,51.82 PB.3 | TF1.2 63.7,45.28 v63.5,45.09
  Bottom 0.152: CS_TF.11 CS_TF.MM
  Bottom 0.406: CS_TF.MM v63.5,45.09 | PB.3 50.55,53.34 51.82,53.34 61.34,43.81 CS_TF.11
PB3/MOSI  (via drill 0.38 pad 0.81)
  Top 0.406: U1.15 38.01,48.93 41.59,52.51 44.64,52.51 PB.4 | TF1.3 59.71,44.18 v59.56,44.32
  Bottom 0.406: PB.4 48.77,52.58 51.31,52.58 v59.56,44.32 67.06,36.83 76.2,36.83 77.47,35.56 77.47,33.02 ICSP.5
PB4/MISO  (via drill 0.38 pad 0.81)
  Top 0.406: U1.16 37.2,49.14 41.27,53.21 42.8,53.21 PB.5 | TF1.7 62.84,39.78 v62.74,39.88
  Bottom 0.406: PB.5 46.99,51.82 50.8,51.82 v62.74,39.88 68.33,34.29 ICSP.1
PB5/SCK  (via drill 0.38 pad 0.81)
  Top 0.406: U1.17 36.01,42.17 36.39,42.55 36.39,49.34 PB.6 | TF1.5 59.37,41.98 v59.31,42.04
  Bottom 0.406: PB.6 45.21,51.05 50.29,51.05 v59.31,42.04 69.6,31.75 ICSP.2
PC0
  Top 0.406: U1.23 34.83,37.37 34.48,37.02 34.48,32.58 39.37,27.69 45.97,27.69 63.5,10.16 PC.1
PC1
  Top 0.406: U1.24 35.36,36.57 35.24,36.45 35.24,32.96 39.75,28.45 46.48,28.45 66.04,8.89 PC.2
PC2
  Top 0.406: U1.25 37.2,32.14 40.13,29.21 46.99,29.21 68.58,7.62 PC.3
PC3
  Top 0.406: U1.26 38.01,32.48 40.51,29.97 47.5,29.97 PC.4
PC4/SDA  (via drill 0.38 pad 0.81)
  Top 0.203: Q1.1 70.61,21.72 71.37,20.95 71.37,18.8 70.42,17.84 R1.1 75.5,17.21 3V3.4
  Top 0.406: U1.27 38.8,32.82 40.89,30.73 48.01,30.73 v53.09,25.65 55.24,27.81 66.93,27.81 73.28,34.16 73.28,37.08 76.2,40.01 76.2,41.4 75.69,41.91 U7.15
  Bottom 0.406: v53.09,25.65 71.12,7.62 72.39,7.62 PC.5 74.93,5.08 76.83,5.08 77.47,5.71 77.47,15.24 3V3.4
PC5/SCL  (via drill 0.38 pad 0.81)
  Top 0.203: Q1.3 68.9,21.27 69.22,20.95 70.61,20.95 70.99,20.57 70.99,19.05 69.6,17.65 R1.2 69.6,16.76 69.85,16.51 73.66,16.51 74.93,15.24
  Top 0.406: U1.28 39.6,33.17 41.27,31.5 48.51,31.5 v53.09,26.92 54.74,28.57 66.55,28.57 72.52,34.54 72.52,39.62 73.53,40.64 U7.16 | PC.6 76.2,13.97 | 76.2,13.97 76.45,14.22 | 76.45,14.22 77.47,15.24 77.47,17.78 3V3.3 | 76.2,13.97 75.95,14.22 | 75.95,14.22 74.93,15.24 | 76.45,14.22 75.95,14.22
  Bottom 0.406: v53.09,26.92 71.63,8.38 74.17,8.38 PC.6
PD0/RXD  (via drill 0.38 pad 0.81)
  Top 0.406: v41.27,36.83 41.2,36.76 U1.30 41.2,33.85 42.04,33.02 69.22,33.02 71.75,35.56 71.75,50.16 PD.1 | R15.1 28.57,27.94 v30.48,29.84
  Bottom 0.406: PD.1 82.55,48.26 82.55,27.94 85.22,25.27 85.22,20.45 J2.3 | v30.48,29.84 34.29,29.84 v41.27,36.83
PD1/TXD  (via drill 0.38 pad 0.81)
  Top 0.406: v42.67,36.83 42.01,36.16 U1.31 42.01,34.2 42.42,33.78 68.96,33.78 70.99,35.81 70.99,51.94 PD.2 | R16.1 27.94,26.04 v30.48,28.57
  Bottom 0.406: PD.2 74.93,53.34 76.33,53.34 81.79,47.88 81.79,23.62 J2.2 | v30.48,28.57 34.42,28.57 v42.67,36.83
PD2
  Top 0.406: PD.3 70.23,53.72 70.23,36.07 68.71,34.54 43.05,34.54 42.8,34.79 U1.32
  Bottom 0.406: !INT.2 77.47,48.26 PD.3
PD3
  Top 0.406: PD.4 69.47,53.72 69.47,38.99 68.07,37.59 51.56,37.59 49.28,35.31 45.97,35.31 44.71,36.57 U1.1
  Bottom 0.406: RST/32K.MM 68.58,45.09 67.94,45.72 67.94,53.98 PD.4
PD4  (via drill 0.38 pad 0.81)
  Top 0.406: U1.2 48.16,37.37 v48.9,38.1 53.98,43.18 53.98,48.39 57.4,51.82 63.25,51.82 PD.5
  Bottom 0.406: 48.26,12.95 POWER_TF.11 47.94,13.27 47.94,37.15 v48.9,38.1
PD5  (via drill 0.38 pad 0.81)
  Top 0.406: U1.9 42.8,47.63 43.5,48.32 52.9,48.32 57.15,52.58 61.47,52.58 PD.6 60.2,57.91 35.18,57.91 31.37,54.1 31.37,38.86 v24.77,32.26
  Bottom 0.406: v24.77,32.26 POWER_BEE.11
PD6
  Top 0.406: U1.10 42.01,47.85 43.18,49.02 52.58,49.02 56.9,53.34 59.69,53.34 PD.7 58.36,57.21 35.62,57.21 32.13,53.72 32.13,19.62 29.84,17.34 MON.3
PD7
  Top 0.406: U1.11 41.2,48.06 42.86,49.72 52.26,49.72 57.15,54.61 PD.8 56.52,56.52 36.07,56.52 32.89,53.34 32.89,18.92 32.38,18.41 MON.2
PULL_H  (via drill 0.38 pad 0.81)
  Top 0.305: R1.5 68.01,15.18 v68.45,14.73 68.83,15.11 R1.6
  Bottom 0.406: 5V.1 77.47,22.86 71.12,22.86 70.1,23.88 68.71,23.88 66.8,21.97 66.8,16.38 v68.45,14.73
RTC!RST  (via drill 0.38 pad 0.81)
  Top 0.406: U7.4 82.55,44.45 80.01,46.99 v76.45,46.99
  Bottom 0.406: v76.45,46.99 70.48,46.99 RST/32K.00
RVIN  (via drill 0.38 pad 0.81)
  Top 0.406: U3.3 20.64,31.43 21.08,30.99 v24.77,30.99 | v48.51,8.26 45.09,8.26 44.77,8.57 U6.1 | U6.3 46.67,10.47 47.62,11.43 v49.78,11.43
  Top 0.61: 44.67,10.13 U6.1
  Top 0.813: v38.73,10.16 C18.+ 38.73,9.08 | D3.- 38.73,5.08 38.73,8.89 | 38.73,8.89 38.73,9.08 | C16.+ U3.1 | C16.+ | Q3.2 38.48,9.14 38.73,8.89 | C16.+ 24.58,29.53 v24.77,29.72 | 44.67,10.13 U2.3 42.86,8.76 42.48,8.38 41.34,8.38 40.96,8.76 U2.1 40.96,9.4 40.7,9.14 | 38.73,9.08 40.64,9.08 40.7,9.14 | 40.7,9.14 40.7,9.02 40.96,8.76
  Bottom 0.152: POWER_BEE.00 POWER_BEE.MM | POWER_TF.00 POWER_TF.MM
  Bottom 0.406: POWER_BEE.MM v24.77,30.99 | v48.51,8.26 POWER_TF.00 | POWER_TF.MM v49.78,11.43
  Bottom 0.813: v24.77,29.72 POWER_BEE.00 27.43,29.72 38.73,18.41 v38.73,10.16
TF_3V3  (via drill 0.38 pad 0.81)
  Top 0.61: U6.5 44.77,14.8 C21.1 44.83,16 45.47,16.64 v48.9,16.64 | C10.1 67.28,43.08 TF1.4 56.54,43.08 C8.1 52.83,40.51 v48.9,36.58
  Bottom 0.61: v48.9,16.64 v48.9,36.58 49.78,37.47 TF3V3.T
TIMEKEEPING  (via drill 0.3 pad 0.64)
  Top 0.406: U7.14 75.82,43.18 76.96,42.04 76.96,38.73 76.58,38.35 C4.2 74.04,35.56 74.04,33.78 65.66,25.4 BAT1.+
  Top 0.61: BAT.T BAT1.+
  other vias: 62.23,25.4
USB5V
  Top 0.254: Q3.1 34.67,9.02 R7.2 37.34,6.35 37.34,4.19 37.72,3.81 40.7,3.81 | 40.7,3.81 41.27,4.38 | 40.7,3.81 41.27,3.81 | 40.7,3.81 41.27,3.24
  Top 0.813: PWR.4 46.99,2.54 D2.+ 41.27,3.81 D3.+
  Top 1.016: PWR.4 53.34,3.81 77.47,3.81 80.64,6.99 80.64,13.34 J2.4
V_REF
  Top 0.406: U1.20 34.91,39.77 C2.2 33.66,41.02 33.66,52.96 35.31,54.61 PB.8
VOL
  Top 0.406: U1.22 34.61,38.17 33.72,37.27 33.72,32.19 39.5,26.42 R12.2
  Top 0.813: R12.2 R13.1 C11.1
XTAL1
  Top 0.406: U1.7 50.01,41.37 C6.2 51.18,45.78 X3.2
XTAL2
  Top 0.406: U1.8 46.23,42.17 C7.2 46.61,45.78 X3.1

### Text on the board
tPlace: PWM | PWM | PWM | PWM | PWM | PWM | TXD | RXD | AREF | GND | 13 | 12 | 11 | 10 | 9 | 8 | 7 | 6 | 5 | 4 | 3 | 2 | 1 | 0 | 1 | V+ | DTR | GND | TXD | CH_READ | OK_READ | BAT_READ | SCL | RXD | SDA | USB5V | - | GND | + | GND | - | + | NC | A0 | A1 | A2 | A3 | SDA | SCL | RESET | 3V3 | GND | GND | ANALOG IN | USB5V
bPlace: PB1 | RTC_!RST | SS | PD3 | PD2 | !INT | PB2 | 32KHz | Seeeduino Stalker | V2.1 by Albert Miao | 25/07/2011 | PD5 | EN | VCC | www.seeedstudio.com | PD4 | EN | VCC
